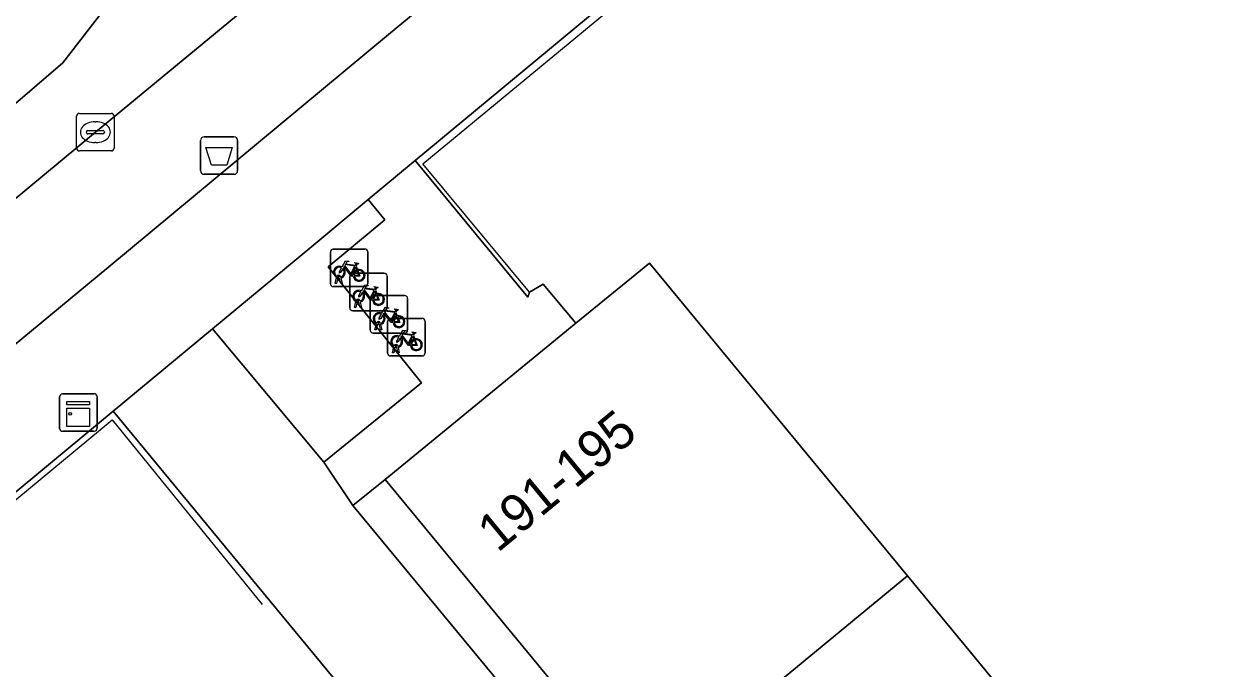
# Model space of a CAD drawing. Extents: x 162344 to 162869, y 381217 to 381818.
# Drawn here: x 162449.62 to 162481.8, y 381732.95 to 381750.16 of the extents above; entities that cross this region are included whole.
import ezdxf

# ---------------------------------------------------------------- set-up
doc = ezdxf.new("R2010")
doc.units = 0
for name, color, linetype in [('IMGEO_Afvalbak', 7, 'Continuous'), ('IMGEO_Berm_groen', 7, 'Continuous'), ('IMGEO_Fietsenrek', 7, 'Continuous'), ('IMGEO_Fietspad_open', 7, 'Continuous'), ('IMGEO_Groenvoorziening', 7, 'Continuous'), ('IMGEO_Hek', 7, 'Continuous'), ('IMGEO_Kast', 7, 'Continuous'), ('IMGEO_Kolk', 7, 'Continuous'), ('IMGEO_Pand', 7, 'Continuous'), ('IMGEO_Pand_nummerreeks', 7, 'Continuous'), ('IMGEO_Rijbaan_lokaal_open', 7, 'Continuous'), ('IMGEO_Voetpad_open', 7, 'Continuous')]:
    doc.layers.add(name, color=color, linetype=linetype)

msp = doc.modelspace()

# ---------------------------------------------------------------- linework, layer by layer
at = {"layer": 'IMGEO_Afvalbak'}
for p, q in [((162454.327, 381746.247), (162454.327, 381747.047)), ((162454.327, 381747.047), (162454.327, 381746.247)), ((162454.427, 381747.147), (162455.217, 381747.147)), ((162455.217, 381747.147), (162454.427, 381747.147)), ((162455.317, 381747.047), (162455.317, 381746.247)), ((162455.317, 381746.247), (162455.317, 381747.047)), ((162455.217, 381746.147), (162454.427, 381746.147)), ((162454.427, 381746.147), (162455.217, 381746.147))]:
    msp.add_line(p, q, dxfattribs=at)
msp.add_lwpolyline([(162454.47, 381746.861), (162455.174, 381746.861), (162455.025, 381746.391), (162454.619, 381746.391), (162454.47, 381746.861)], dxfattribs=at)
for centre, start, end in [((162454.427, 381747.047), 90, 180), ((162454.427, 381747.047), 90, 180), ((162455.217, 381747.047), 0, 90), ((162455.217, 381747.047), 360, 90), ((162454.427, 381746.247), 180, 270), ((162454.427, 381746.247), 180, 270), ((162455.217, 381746.247), 270, 0), ((162455.217, 381746.247), 270, 0)]:
    msp.add_arc(centre, 0.1, start, end, dxfattribs=at)
at = {"layer": 'IMGEO_Berm_groen'}
msp.add_lwpolyline([(162485.569, 381771.54), (162486.346, 381772.165), (162499.033, 381781.642), (162500.475, 381782.734), (162498.716, 381785.09), (162498.222, 381784.754), (162492.604, 381780.797), (162491.487, 381780.055), (162488.724, 381777.94), (162487.946, 381777.388), (162484.993, 381774.972), (162478.211, 381769.449), (162471.4, 381763.826), (162457.878, 381752.522), (162455.794, 381750.801), (162451.521, 381747.272), (162447.905, 381744.275), (162433.442, 381732.29), (162428.876, 381728.513), (162426.389, 381726.442), (162426.314, 381726.37), (162428.207, 381724.094), (162451.823, 381743.637), (162459.348, 381749.88)], close=True, dxfattribs=at)
at = {"layer": 'IMGEO_Fietsenrek'}
for p, q in [((162457.867, 381744.151), (162458.708, 381744.151)), ((162458.708, 381744.151), (162457.867, 381744.151)), ((162458.792, 381744.076), (162458.792, 381743.235)), ((162458.792, 381743.235), (162458.792, 381744.076)), ((162457.792, 381743.226), (162457.792, 381744.067)), ((162457.792, 381744.067), (162457.792, 381743.226)), ((162458.383, 381743.508), (162459.224, 381743.508)), ((162459.224, 381743.508), (162458.383, 381743.508)), ((162458.479, 381743.7), (162458.515, 381743.605)), ((162459.308, 381743.433), (162459.308, 381742.592)), ((162459.308, 381742.592), (162459.308, 381743.433)), ((162458.717, 381743.151), (162457.876, 381743.151)), ((162457.876, 381743.151), (162458.717, 381743.151)), ((162457.919, 381743.235), (162457.958, 381743.395)), ((162457.953, 381743.235), (162457.919, 381743.235)), ((162457.988, 381743.383), (162457.953, 381743.235)), ((162458.03, 381743.407), (162458.029, 381743.411)), ((162458.071, 381743.235), (162458.037, 381743.377)), ((162458.061, 381743.418), (162458.062, 381743.411)), ((162458.069, 381743.381), (162458.104, 381743.235)), ((162458.104, 381743.235), (162458.071, 381743.235)), ((162458.308, 381742.583), (162458.308, 381743.424)), ((162458.308, 381743.424), (162458.308, 381742.583)), ((162458.855, 381741.987), (162458.855, 381742.828)), ((162458.855, 381742.828), (162458.855, 381741.987)), ((162458.93, 381742.912), (162459.771, 381742.912)), ((162459.771, 381742.912), (162458.93, 381742.912)), ((162458.995, 381743.057), (162459.031, 381742.962)), ((162459.855, 381742.837), (162459.855, 381741.996)), ((162459.855, 381741.996), (162459.855, 381742.837)), ((162459.233, 381742.508), (162458.392, 381742.508)), ((162458.392, 381742.508), (162459.233, 381742.508)), ((162458.435, 381742.592), (162458.474, 381742.752)), ((162458.469, 381742.592), (162458.435, 381742.592)), ((162458.504, 381742.74), (162458.469, 381742.592)), ((162458.546, 381742.764), (162458.545, 381742.768)), ((162458.587, 381742.592), (162458.553, 381742.734)), ((162458.577, 381742.775), (162458.578, 381742.768)), ((162458.585, 381742.738), (162458.62, 381742.592)), ((162458.62, 381742.592), (162458.587, 381742.592)), ((162458.982, 381741.996), (162459.021, 381742.156)), ((162459.051, 381742.144), (162459.016, 381741.996)), ((162459.093, 381742.168), (162459.092, 381742.172)), ((162459.124, 381742.179), (162459.125, 381742.172)), ((162459.321, 381741.374), (162459.321, 381742.215)), ((162459.321, 381742.215), (162459.321, 381741.374)), ((162459.396, 381742.299), (162460.237, 381742.299)), ((162460.237, 381742.299), (162459.396, 381742.299)), ((162459.542, 381742.461), (162459.578, 381742.366)), ((162460.321, 381742.224), (162460.321, 381741.383)), ((162460.321, 381741.383), (162460.321, 381742.224)), ((162459.78, 381741.912), (162458.939, 381741.912)), ((162458.939, 381741.912), (162459.78, 381741.912)), ((162459.016, 381741.996), (162458.982, 381741.996)), ((162459.134, 381741.996), (162459.1, 381742.138)), ((162459.132, 381742.142), (162459.167, 381741.996)), ((162459.167, 381741.996), (162459.134, 381741.996)), ((162460.008, 381741.848), (162460.044, 381741.753)), ((162459.448, 381741.383), (162459.487, 381741.543)), ((162459.517, 381741.531), (162459.482, 381741.383)), ((162459.559, 381741.555), (162459.558, 381741.559)), ((162459.6, 381741.383), (162459.566, 381741.525)), ((162459.59, 381741.566), (162459.591, 381741.559)), ((162459.598, 381741.529), (162459.633, 381741.383)), ((162460.246, 381741.299), (162459.405, 381741.299)), ((162459.405, 381741.299), (162460.246, 381741.299)), ((162459.482, 381741.383), (162459.448, 381741.383)), ((162459.633, 381741.383), (162459.6, 381741.383))]:
    msp.add_line(p, q, dxfattribs=at)
for points in [[(162458.105, 381743.677), (162458.2, 381743.841), (162458.286, 381743.827), (162458.288, 381743.818), (162458.232, 381743.807), (162458.205, 381743.762), (162458.461, 381743.721)], [(162458.461, 381743.721), (162458.486, 381743.77), (162458.48, 381743.774), (162458.457, 381743.778), (162458.445, 381743.785), (162458.444, 381743.788), (162458.446, 381743.793), (162458.541, 381743.778), (162458.543, 381743.768), (162458.533, 381743.755), (162458.521, 381743.749), (162458.507, 381743.755), (162458.479, 381743.7)], [(162458.126, 381743.625), (162458.074, 381743.535), (162458.034, 381743.51), (162458.035, 381743.557), (162458.09, 381743.651)], [(162458.401, 381743.433), (162458.351, 381743.433), (162458.16, 381743.684), (162458.141, 381743.652)], [(162458.448, 381743.696), (162458.191, 381743.737), (162458.174, 381743.708), (162458.341, 381743.488), (162458.448, 381743.696)], [(162458.496, 381743.598), (162458.466, 381743.675), (162458.357, 381743.457), (162458.4, 381743.457)], [(162458.43, 381743.457), (162458.55, 381743.456), (162458.506, 381743.57)], [(162458.526, 381743.577), (162458.581, 381743.432), (162458.431, 381743.432)], [(162458.621, 381743.034), (162458.716, 381743.198), (162458.802, 381743.184), (162458.804, 381743.175), (162458.748, 381743.164), (162458.721, 381743.119), (162458.977, 381743.078)], [(162458.977, 381743.078), (162459.002, 381743.127), (162458.996, 381743.131), (162458.973, 381743.135), (162458.961, 381743.142), (162458.96, 381743.145), (162458.962, 381743.15), (162459.057, 381743.135), (162459.059, 381743.125), (162459.049, 381743.112), (162459.037, 381743.106), (162459.023, 381743.112), (162458.995, 381743.057)], [(162458.642, 381742.982), (162458.59, 381742.892), (162458.55, 381742.867), (162458.551, 381742.914), (162458.606, 381743.008)], [(162458.917, 381742.79), (162458.867, 381742.79), (162458.676, 381743.041), (162458.657, 381743.009)], [(162458.964, 381743.053), (162458.707, 381743.094), (162458.69, 381743.065), (162458.857, 381742.845), (162458.964, 381743.053)], [(162459.012, 381742.955), (162458.982, 381743.032), (162458.873, 381742.814), (162458.916, 381742.814)], [(162458.946, 381742.814), (162459.066, 381742.813), (162459.022, 381742.927)], [(162459.042, 381742.934), (162459.097, 381742.789), (162458.947, 381742.789)], [(162459.168, 381742.438), (162459.263, 381742.602), (162459.349, 381742.588), (162459.351, 381742.579), (162459.295, 381742.568), (162459.268, 381742.523), (162459.524, 381742.482)], [(162459.511, 381742.457), (162459.254, 381742.498), (162459.237, 381742.469), (162459.404, 381742.249), (162459.511, 381742.457)], [(162459.524, 381742.482), (162459.549, 381742.531), (162459.543, 381742.535), (162459.52, 381742.539), (162459.508, 381742.546), (162459.507, 381742.549), (162459.509, 381742.554), (162459.604, 381742.539), (162459.606, 381742.529), (162459.596, 381742.516), (162459.584, 381742.51), (162459.57, 381742.516), (162459.542, 381742.461)], [(162459.189, 381742.386), (162459.137, 381742.296), (162459.097, 381742.271), (162459.098, 381742.318), (162459.153, 381742.412)], [(162459.464, 381742.194), (162459.414, 381742.194), (162459.223, 381742.445), (162459.204, 381742.413)], [(162459.559, 381742.359), (162459.529, 381742.436), (162459.42, 381742.218), (162459.463, 381742.218)], [(162459.493, 381742.218), (162459.613, 381742.217), (162459.569, 381742.331)], [(162459.589, 381742.338), (162459.644, 381742.193), (162459.494, 381742.193)], [(162459.634, 381741.825), (162459.729, 381741.989), (162459.815, 381741.975), (162459.817, 381741.966), (162459.761, 381741.955), (162459.734, 381741.91), (162459.99, 381741.869)], [(162459.93, 381741.581), (162459.88, 381741.581), (162459.689, 381741.832), (162459.67, 381741.8)], [(162459.977, 381741.844), (162459.72, 381741.885), (162459.703, 381741.856), (162459.87, 381741.636), (162459.977, 381741.844)], [(162460.025, 381741.746), (162459.995, 381741.823), (162459.886, 381741.605), (162459.929, 381741.605)], [(162459.99, 381741.869), (162460.015, 381741.918), (162460.009, 381741.922), (162459.986, 381741.926), (162459.974, 381741.933), (162459.973, 381741.936), (162459.975, 381741.941), (162460.07, 381741.926), (162460.072, 381741.916), (162460.062, 381741.903), (162460.05, 381741.897), (162460.036, 381741.903), (162460.008, 381741.848)], [(162459.655, 381741.773), (162459.603, 381741.683), (162459.563, 381741.658), (162459.564, 381741.705), (162459.619, 381741.799)], [(162459.959, 381741.605), (162460.079, 381741.604), (162460.035, 381741.718)], [(162460.055, 381741.725), (162460.11, 381741.58), (162459.96, 381741.58)]]:
    msp.add_lwpolyline(points, dxfattribs=at)
for centre, radius, start, end in [((162457.87, 381744.073), 0.0779, 92.4484, 184.2845), ((162457.87, 381744.073), 0.0779, 92.4484, 184.2845), ((162458.714, 381744.073), 0.0779, 2.4484, 94.2845), ((162458.714, 381744.073), 0.0779, 2.4484, 94.2845), ((162458.032, 381743.536), 0.159, 62.6766, 242.1369), ((162458.032, 381743.536), 0.129, 63.3192, 238.903), ((162458.012, 381743.407), 0.0499, 12.8025, 158.6934), ((162458.032, 381743.536), 0.129, 283.6043, 43.4302), ((162458.032, 381743.536), 0.159, 283.5766, 46.6042), ((162458.386, 381743.43), 0.0779, 92.4484, 184.2845), ((162458.386, 381743.43), 0.0779, 92.4484, 184.2845), ((162458.559, 381743.452), 0.159, 113.3408, 178.3217), ((162458.559, 381743.452), 0.159, 187.0065, 105.7708), ((162458.559, 381743.452), 0.129, 113.923, 177.9556), ((162458.559, 381743.452), 0.129, 188.6715, 104.5883), ((162459.23, 381743.43), 0.0779, 2.4484, 94.2845), ((162459.23, 381743.43), 0.0779, 2.4484, 94.2845), ((162457.87, 381743.229), 0.0779, 182.4484, 274.2845), ((162457.87, 381743.229), 0.0779, 182.4484, 274.2845), ((162458.032, 381743.536), 0.159, 253.9967, 271.7867), ((162458.012, 381743.407), 0.0174, 12.8025, 163.4502), ((162458.032, 381743.536), 0.129, 253.415, 269.0204), ((162458.714, 381743.229), 0.0779, 272.4484, 4.2845), ((162458.714, 381743.229), 0.0779, 272.4484, 4.2845), ((162458.548, 381742.893), 0.159, 62.6766, 242.1369), ((162458.548, 381742.893), 0.129, 63.3192, 238.903), ((162458.528, 381742.764), 0.0499, 12.8025, 158.6934), ((162458.548, 381742.893), 0.129, 283.6043, 43.4302), ((162458.548, 381742.893), 0.159, 283.5766, 46.6042), ((162458.933, 381742.834), 0.0779, 92.4484, 184.2845), ((162458.933, 381742.834), 0.0779, 92.4484, 184.2845), ((162459.075, 381742.809), 0.159, 113.3408, 178.3217), ((162459.075, 381742.809), 0.159, 187.0065, 105.7708), ((162459.075, 381742.809), 0.129, 113.923, 177.9556), ((162459.075, 381742.809), 0.129, 188.6715, 104.5883), ((162459.777, 381742.834), 0.0779, 2.4484, 94.2845), ((162459.777, 381742.834), 0.0779, 2.4484, 94.2845), ((162458.386, 381742.586), 0.0779, 182.4484, 274.2845), ((162458.386, 381742.586), 0.0779, 182.4484, 274.2845), ((162458.548, 381742.893), 0.159, 253.9967, 271.7867), ((162458.528, 381742.764), 0.0174, 12.8025, 163.4502), ((162458.548, 381742.893), 0.129, 253.415, 269.0204), ((162459.23, 381742.586), 0.0779, 272.4484, 4.2845), ((162459.23, 381742.586), 0.0779, 272.4484, 4.2845), ((162459.095, 381742.297), 0.159, 62.6766, 242.1369), ((162459.095, 381742.297), 0.129, 63.3192, 238.903), ((162459.075, 381742.168), 0.0499, 12.8025, 158.6934), ((162459.095, 381742.297), 0.159, 253.9967, 271.7867), ((162459.075, 381742.168), 0.0174, 12.8025, 163.4502), ((162459.095, 381742.297), 0.129, 253.415, 269.0204), ((162459.095, 381742.297), 0.129, 283.6043, 43.4302), ((162459.095, 381742.297), 0.159, 283.5766, 46.6042), ((162459.399, 381742.221), 0.0779, 92.4484, 184.2845), ((162459.399, 381742.221), 0.0779, 92.4484, 184.2845), ((162459.622, 381742.213), 0.159, 113.3408, 178.3217), ((162459.622, 381742.213), 0.159, 187.0065, 105.7708), ((162459.622, 381742.213), 0.129, 113.923, 177.9556), ((162459.622, 381742.213), 0.129, 188.6715, 104.5883), ((162460.243, 381742.221), 0.0779, 2.4484, 94.2845), ((162460.243, 381742.221), 0.0779, 2.4484, 94.2845), ((162458.933, 381741.99), 0.0779, 182.4484, 274.2845), ((162458.933, 381741.99), 0.0779, 182.4484, 274.2845), ((162459.561, 381741.684), 0.159, 62.6766, 242.1369), ((162459.777, 381741.99), 0.0779, 272.4484, 4.2845), ((162459.777, 381741.99), 0.0779, 272.4484, 4.2845), ((162459.561, 381741.684), 0.129, 63.3192, 238.903), ((162459.541, 381741.555), 0.0499, 12.8025, 158.6934), ((162459.561, 381741.684), 0.159, 253.9967, 271.7867), ((162459.541, 381741.555), 0.0174, 12.8025, 163.4502), ((162459.561, 381741.684), 0.129, 253.415, 269.0204), ((162459.561, 381741.684), 0.129, 283.6043, 43.4302), ((162459.561, 381741.684), 0.159, 283.5766, 46.6042), ((162460.088, 381741.6), 0.159, 113.3408, 178.3217), ((162460.088, 381741.6), 0.159, 187.0065, 105.7708), ((162460.088, 381741.6), 0.129, 113.923, 177.9556), ((162460.088, 381741.6), 0.129, 188.6715, 104.5883), ((162459.399, 381741.377), 0.0779, 182.4484, 274.2845), ((162459.399, 381741.377), 0.0779, 182.4484, 274.2845), ((162460.243, 381741.377), 0.0779, 272.4484, 4.2845), ((162460.243, 381741.377), 0.0779, 272.4484, 4.2845)]:
    msp.add_arc(centre, radius, start, end, dxfattribs=at)
at = {"layer": 'IMGEO_Fietspad_open'}
msp.add_lwpolyline([(162451.521, 381747.272), (162455.794, 381750.801), (162453.794, 381753.188), (162450.654, 381749.123), (162425.365, 381727.418), (162426.277, 381726.338), (162426.314, 381726.37), (162426.389, 381726.442), (162428.876, 381728.513), (162433.442, 381732.29), (162447.905, 381744.275)], close=True, dxfattribs=at)
at = {"layer": 'IMGEO_Groenvoorziening'}
for points in [[(162496.987, 381737.052), (162495.038, 381735.498), (162493.26, 381737.631), (162495.209, 381739.256), (162488.397, 381747.426), (162486.513, 381745.893), (162484.735, 381748.042), (162486.667, 381749.611), (162477.365, 381760.866), (162460.058, 381746.513), (162463.062, 381742.868), (162463.106, 381743.006), (162463.476, 381743.219), (162464.348, 381742.174), (162466.307, 381743.777), (162473.193, 381735.435), (162480.005, 381727.183), (162486.816, 381718.931), (162493.628, 381710.68), (162500.056, 381702.892)], [(162471.549, 381716.061), (162469.643, 381714.467), (162467.863, 381716.602), (162469.783, 381718.202), (162463.314, 381726.102), (162461.333, 381724.518), (162459.563, 381726.678), (162461.541, 381728.274), (162451.996, 381739.827), (162449.119, 381737.441), (162434.479, 381725.379), (162437.492, 381721.752), (162438.041, 381722.212), (162438.864, 381721.224), (162441.001, 381722.982), (162447.798, 381714.718), (162454.595, 381706.454), (162461.391, 381698.19), (162468.188, 381689.926), (162474.743, 381681.955)]]:
    msp.add_lwpolyline(points, dxfattribs=at)
for points in [[(162457.735, 381743.677), (162459.249, 381744.932), (162458.802, 381745.471), (162457.296, 381744.222), (162454.645, 381742.024), (162457.62, 381738.466), (162460.226, 381740.585)], [(162459.252, 381738.006), (162458.388, 381737.311), (162465.316, 381728.939), (162466.159, 381729.634)]]:
    msp.add_lwpolyline(points, close=True, dxfattribs=at)
at = {"layer": 'IMGEO_Hek'}
for points in [[(162463.106, 381743.006), (162460.263, 381746.426), (162477.364, 381760.553), (162481.17, 381755.868)], [(162437.475, 381721.871), (162434.659, 381725.263), (162451.967, 381739.596), (162455.968, 381734.665)]]:
    msp.add_lwpolyline(points, dxfattribs=at)
at = {"layer": 'IMGEO_Kast'}
for p, q in [((162450.641, 381740.291), (162451.482, 381740.291)), ((162451.482, 381740.291), (162450.641, 381740.291)), ((162451.566, 381740.216), (162451.566, 381739.375)), ((162451.566, 381739.375), (162451.566, 381740.216)), ((162450.566, 381739.366), (162450.566, 381740.207)), ((162450.566, 381740.207), (162450.566, 381739.366)), ((162451.491, 381739.291), (162450.65, 381739.291)), ((162450.65, 381739.291), (162451.491, 381739.291))]:
    msp.add_line(p, q, dxfattribs=at)
for points in [[(162450.761, 381740.081), (162451.361, 381740.081), (162451.361, 381739.996), (162450.761, 381739.996), (162450.761, 381740.081)], [(162450.761, 381739.906), (162451.361, 381739.906), (162451.361, 381739.417), (162450.761, 381739.417), (162450.761, 381739.906)]]:
    msp.add_lwpolyline(points, dxfattribs=at)
msp.add_circle((162450.845, 381739.755), 0.0377, dxfattribs=at)
for centre, start, end in [((162450.644, 381740.213), 92.4484, 184.2845), ((162450.644, 381740.213), 92.4484, 184.2845), ((162451.488, 381740.213), 2.4484, 94.2845), ((162451.488, 381740.213), 2.4484, 94.2845), ((162450.644, 381739.369), 182.4484, 274.2845), ((162450.644, 381739.369), 182.4484, 274.2845), ((162451.488, 381739.369), 272.4484, 4.2845), ((162451.488, 381739.369), 272.4484, 4.2845)]:
    msp.add_arc(centre, 0.0779, start, end, dxfattribs=at)
at = {"layer": 'IMGEO_Kolk'}
for p, q in [((162451.02, 381746.846), (162451.02, 381747.698)), ((162451.095, 381747.772), (162451.947, 381747.772)), ((162452.021, 381747.698), (162452.021, 381746.846)), ((162451.322, 381747.315), (162451.72, 381747.315)), ((162451.508, 381747.552), (162451.533, 381747.552)), ((162451.279, 381747.266), (162451.279, 381747.278)), ((162451.717, 381747.229), (162451.319, 381747.229)), ((162451.531, 381746.992), (162451.506, 381746.992)), ((162451.763, 381747.278), (162451.763, 381747.266)), ((162451.947, 381746.772), (162451.095, 381746.772))]:
    msp.add_line(p, q, dxfattribs=at)
for points in [[(162451.02, 381746.846), (162451.02, 381747.698)], [(162451.095, 381747.772), (162451.947, 381747.772)], [(162452.021, 381747.698), (162452.021, 381746.846)], [(162451.947, 381746.772), (162451.095, 381746.772)]]:
    msp.add_lwpolyline(points, dxfattribs=at)
for centre, radius, start, end in [((162451.097, 381747.696), 0.0765, 91.552, 178.448), ((162451.097, 381747.696), 0.0765, 91.552, 178.448), ((162451.945, 381747.696), 0.0765, 1.552, 88.448), ((162451.945, 381747.696), 0.0765, 1.552, 88.448), ((162451.319, 381747.275), 0.0403, 85.8775, 175.7526), ((162451.724, 381747.277), 0.0386, 1.7309, 96.639), ((162451.316, 381747.265), 0.0366, 178.938, 274.7102), ((162451.72, 381747.272), 0.043, 264.8664, 352.4533), ((162451.097, 381746.848), 0.0765, 181.552, 268.448), ((162451.097, 381746.848), 0.0765, 181.552, 268.448), ((162451.945, 381746.848), 0.0765, 271.552, 358.448), ((162451.945, 381746.848), 0.0765, 271.552, 358.448)]:
    msp.add_arc(centre, radius, start, end, dxfattribs=at)
for centre, major_axis, ratio, start_param, end_param in [((162451.507, 381747.272), (-0.387, 0.002), 0.722429, 4.712389, 7.853982), ((162451.532, 381747.272), (-0.39, 0.002), 0.717154, 1.570796, 4.712389)]:
    msp.add_ellipse(centre, major_axis=major_axis, ratio=ratio, start_param=start_param, end_param=end_param, dxfattribs=at)
at = {"layer": 'IMGEO_Pand'}
for points in [[(162473.193, 381735.435), (162466.307, 381743.777), (162464.348, 381742.174), (162459.252, 381738.006), (162466.159, 381729.634)], [(162473.193, 381735.435), (162466.159, 381729.634), (162468.393, 381726.927), (162472.969, 381721.38), (162480.005, 381727.183)]]:
    msp.add_lwpolyline(points, close=True, dxfattribs=at)
at = {"layer": 'IMGEO_Rijbaan_lokaal_open'}
msp.add_lwpolyline([(162444.009, 381746.21), (162425.507, 381730.862), (162423.709, 381729.379), (162425.365, 381727.418), (162450.654, 381749.123), (162453.794, 381753.188)], dxfattribs=at)
at = {"layer": 'IMGEO_Voetpad_open'}
for points in [[(162516.423, 381797.237), (162499.898, 381785.893), (162498.927, 381785.234), (162498.716, 381785.09), (162500.475, 381782.734), (162499.033, 381781.642), (162486.346, 381772.165), (162485.569, 381771.54), (162459.348, 381749.88), (162451.823, 381743.637), (162428.207, 381724.094), (162426.314, 381726.37), (162426.277, 381726.338), (162424.054, 381724.411)], [(162424.437, 381718.682), (162424.917, 381718.008), (162425.009, 381717.878), (162427.504, 381719.918), (162429.68, 381721.488), (162429.986, 381721.677), (162431.674, 381723.068), (162433.402, 381724.491), (162434.479, 381725.379), (162449.119, 381737.441), (162451.996, 381739.827), (162454.645, 381742.024), (162457.296, 381744.222), (162458.802, 381745.471), (162460.058, 381746.513), (162477.365, 381760.866)]]:
    msp.add_lwpolyline(points, dxfattribs=at)
for points in [[(162464.348, 381742.174), (162463.476, 381743.219), (162463.106, 381743.006), (162463.062, 381742.868), (162460.058, 381746.513), (162458.802, 381745.471), (162459.249, 381744.932), (162457.735, 381743.677), (162460.226, 381740.585), (162457.62, 381738.466), (162458.388, 381737.311), (162459.252, 381738.006)], [(162474.375, 381717.99), (162472.137, 381720.694), (162467.553, 381726.234), (162465.316, 381728.939), (162458.388, 381737.311), (162457.62, 381738.466), (162454.645, 381742.024), (162451.996, 381739.827), (162461.541, 381728.274), (162463.314, 381726.102), (162469.783, 381718.202), (162471.549, 381716.061), (162476.506, 381710.061), (162478.262, 381707.898), (162483.232, 381701.86), (162484.979, 381699.692), (162489.486, 381694.198), (162492.218, 381696.426), (162488.017, 381701.503), (162485.78, 381704.207), (162481.196, 381709.747), (162478.958, 381712.451)]]:
    msp.add_lwpolyline(points, close=True, dxfattribs=at)

# ---------------------------------------------------------------- texts
at = {"layer": 'IMGEO_Pand_nummerreeks'}
msp.add_text('191-195', height=1, rotation=39.5235, dxfattribs=at).set_placement((162462.257, 381736.034))

doc.saveas('drawing.dxf')
